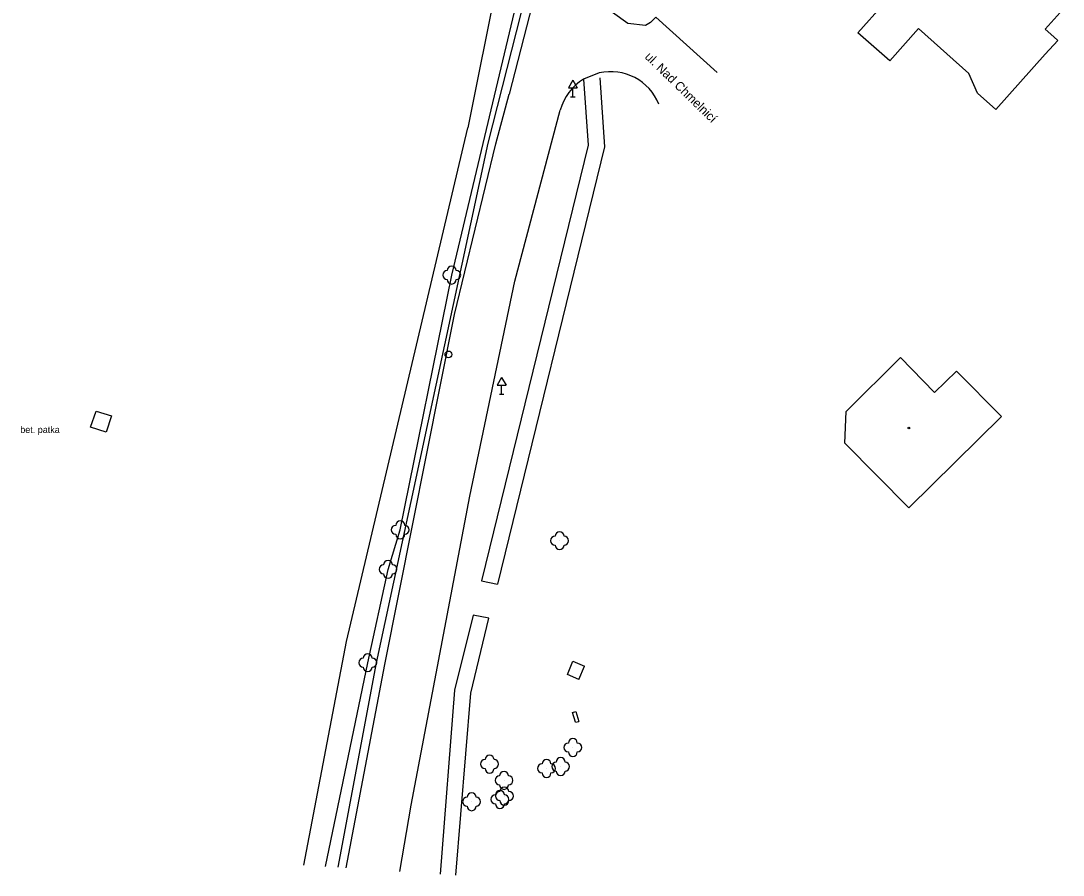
# Model space of a CAD drawing. Extents: x -736687 to -734487, y -1145223 to -1142795.
# Drawn here: x -736687.1 to -736570.8, y -1144307.6 to -1144212.3 of the extents above; entities that cross this region are included whole.
import ezdxf

# ---------------------------------------------------------------- set-up
doc = ezdxf.new("R2010")
doc.units = 0
for name, color, linetype in [('BUDOVY_MĚŘ', 7, 'Continuous'), ('BUOVY_NEMĚŘ', 7, 'Continuous'), ('MAP_ZN_BP', 7, 'Continuous'), ('NÁZVY_ULIC_TOK_SMĚR', 7, 'Continuous'), ('POMOC_POPIS', 7, 'Continuous'), ('ROZHRANÍ_PLOCH', 7, 'Continuous'), ('VÝŠKOPIS', 7, 'Continuous'), ('ZELEŇ', 7, 'Continuous'), ('ZN_BUDOV', 7, 'Continuous'), ('ZN_DOPLŇKOVÉ', 7, 'Continuous')]:
    doc.layers.add(name, color=color, linetype=linetype)

msp = doc.modelspace()

# ---------------------------------------------------------------- linework, layer by layer
at = {"layer": 'BUDOVY_MĚŘ'}
for points in [[(-736593.7, -1144213.67), (-736582.24, -1144200.86), (-736570.79, -1144211.03), (-736572.78, -1144213.27), (-736571.83, -1144214.13)], [(-736572.8, -1144216.07), (-736578.3, -1144222.23), (-736580.34, -1144220.41), (-736581.31, -1144218.21), (-736586.93, -1144213.21), (-736590.14, -1144216.81), (-736593.7, -1144213.67)], [(-736588.01, -1144266.66), (-736595.16, -1144259.45), (-736595, -1144255.91), (-736588.96, -1144249.9), (-736585.15, -1144253.79), (-736582.71, -1144251.42), (-736577.69, -1144256.48), (-736588.01, -1144266.66)], [(-736625.54, -1144289.49), (-736625.18, -1144289.39)], [(-736625.21, -1144290.59), (-736625.54, -1144289.49)], [(-736625.18, -1144289.39), (-736624.85, -1144290.49)], [(-736625.21, -1144290.59), (-736624.85, -1144290.49)]]:
    msp.add_lwpolyline(points, dxfattribs=at)
at = {"layer": 'BUOVY_NEMĚŘ'}
msp.add_lwpolyline([(-736571.83, -1144214.13), (-736571.39, -1144214.52), (-736572.8, -1144216.07)], dxfattribs=at)
at = {"layer": 'MAP_ZN_BP'}
for radius in [0.375, 0.0005]:
    msp.add_circle((-736639.41, -1144249.551), radius, dxfattribs=at)
at = {"layer": 'ROZHRANÍ_PLOCH'}
for points in [[(-736623.31, -1144182.81), (-736627.12, -1144199.12), (-736632.63, -1144220.51)], [(-736609.4, -1144218.09), (-736616.27, -1144211.93), (-736616.85, -1144212.54), (-736617.41, -1144212.85), (-736619.37, -1144212.64), (-736621.08, -1144211.41)], [(-736622.57, -1144218.16), (-736624.32, -1144218.84)], [(-736624.32, -1144218.84), (-736623.8, -1144226.23), (-736635.7, -1144274.81), (-736633.94, -1144275.19)], [(-736622.52, -1144218.71), (-736621.99, -1144226.39), (-736633.94, -1144275.19)], [(-736634.13, -1144226.08), (-736632.63, -1144220.51)], [(-736632.01, -1144241.38), (-736626.94, -1144222.31)], [(-736638.72, -1144245.11), (-736634.13, -1144226.08)], [(-736637, -1144265.35), (-736632.01, -1144241.38)], [(-736646.51, -1144284.13), (-736638.72, -1144245.11)], [(-736643.56, -1144299.82), (-736637, -1144265.35)], [(-736634.88, -1144278.99), (-736636.65, -1144278.63), (-736638.72, -1144286.99), (-736640.32, -1144307.53)], [(-736638.58, -1144307.64), (-736636.92, -1144287.35), (-736634.88, -1144278.99)], [(-736650.84, -1144306.82), (-736646.51, -1144284.13)], [(-736644.82, -1144307.23), (-736643.56, -1144299.82)]]:
    msp.add_lwpolyline(points, dxfattribs=at)
for centre, radius, start, end in [((-736621.285, -1144223.814), 5.798, 22.02059, 102.80325), ((-736621.233, -1144223.895), 5.923, 121.41103, 164.48021)]:
    msp.add_arc(centre, radius, start, end, dxfattribs=at)
at = {"layer": 'VÝŠKOPIS'}
for points in [[(-736639.04, -1144240.7), (-736625.25, -1144182.84)], [(-736634.99, -1144226), (-736628.09, -1144198.92)], [(-736647.44, -1144283.94), (-736634.99, -1144226)], [(-736644.79, -1144269.12), (-736639.04, -1144240.7)], [(-736646.15, -1144273.53), (-736644.79, -1144269.12)], [(-736648.41, -1144283.94), (-736646.15, -1144273.53)], [(-736653.133, -1144306.67), (-736648.41, -1144283.94)], [(-736651.715, -1144306.765), (-736647.44, -1144283.94)]]:
    msp.add_lwpolyline(points, dxfattribs=at)
at = {"layer": 'ZELEŇ'}
for points in [[(-736628.62, -1144184.61), (-736633.96, -1144207.91), (-736637.24, -1144224.27)], [(-736650.78, -1144281.58), (-736637.24, -1144224.27)], [(-736655.56, -1144306.51), (-736650.78, -1144281.58)]]:
    msp.add_lwpolyline(points, dxfattribs=at)
for centre in [(-736639.04, -1144240.7), (-736644.79, -1144269.12), (-736627, -1144270.33), (-736646.15, -1144273.53), (-736648.41, -1144283.94), (-736625.52, -1144293.4), (-736634.82, -1144295.25), (-736628.46, -1144295.74), (-736626.88, -1144295.53), (-736633.2, -1144297.07), (-736636.82, -1144299.45), (-736633.66, -1144299.19), (-736633.16, -1144298.82)]:
    msp.add_circle(centre, 0.0005, dxfattribs=at)
for centre, start, end in [((-736639.54, -1144240.7), 89.99999, 269.99999), ((-736639.04, -1144240.2), 0, 179.99999), ((-736638.54, -1144240.7), 270, 89.99999), ((-736639.04, -1144241.2), 179.99999, 359.99999), ((-736644.79, -1144268.62), 0, 179.99999), ((-736645.29, -1144269.12), 89.99999, 269.99999), ((-736644.29, -1144269.12), 270, 89.99999), ((-736627, -1144269.83), 0, 179.99999), ((-736644.79, -1144269.62), 179.99999, 359.99999), ((-736627.5, -1144270.33), 89.99999, 269.99999), ((-736626.5, -1144270.33), 270, 89.99999), ((-736627, -1144270.83), 179.99999, 359.99999), ((-736646.15, -1144273.03), 0, 179.99999), ((-736646.65, -1144273.53), 89.99999, 269.99999), ((-736646.15, -1144274.03), 179.99999, 359.99999), ((-736645.65, -1144273.53), 270, 89.99999), ((-736648.41, -1144283.44), 0, 179.99999), ((-736648.91, -1144283.94), 89.99999, 269.99999), ((-736648.41, -1144284.44), 179.99999, 359.99999), ((-736647.91, -1144283.94), 270, 89.99999), ((-736625.52, -1144292.9), 0, 179.99999), ((-736626.02, -1144293.4), 89.99999, 269.99999), ((-736625.02, -1144293.4), 270, 89.99999), ((-736635.32, -1144295.25), 89.99999, 269.99999), ((-736634.82, -1144294.75), 0, 179.99999), ((-736634.32, -1144295.25), 270, 89.99999), ((-736628.46, -1144295.24), 0, 179.99999), ((-736626.88, -1144295.03), 0, 179.99999), ((-736625.52, -1144293.9), 179.99999, 359.99999), ((-736634.82, -1144295.75), 179.99999, 359.99999), ((-736633.2, -1144296.57), 0, 179.99999), ((-736628.96, -1144295.74), 89.99999, 269.99999), ((-736627.96, -1144295.74), 270, 89.99999), ((-736627.38, -1144295.53), 89.99999, 269.99999), ((-736626.88, -1144296.03), 179.99999, 359.99999), ((-736626.38, -1144295.53), 270, 89.99999), ((-736633.7, -1144297.07), 89.99999, 269.99999), ((-736632.7, -1144297.07), 270, 89.99999), ((-736628.46, -1144296.24), 179.99999, 359.99999), ((-736636.82, -1144298.95), 0, 179.99999), ((-736633.66, -1144298.69), 0, 179.99999), ((-736633.66, -1144298.82), 89.99999, 269.99999), ((-736633.2, -1144297.57), 179.99999, 359.99999), ((-736633.16, -1144298.32), 0, 179.99999), ((-736632.66, -1144298.82), 270, 89.99999), ((-736637.32, -1144299.45), 89.99999, 269.99999), ((-736636.32, -1144299.45), 270, 89.99999), ((-736634.16, -1144299.19), 89.99999, 269.99999), ((-736633.16, -1144299.32), 179.99999, 359.99999), ((-736633.16, -1144299.19), 270, 89.99999), ((-736636.82, -1144299.95), 179.99999, 359.99999), ((-736633.66, -1144299.69), 179.99999, 359.99999)]:
    msp.add_arc(centre, 0.5, start, end, dxfattribs=at)
at = {"layer": 'ZN_BUDOV'}
msp.add_circle((-736588.01, -1144257.77), 0.0875, dxfattribs=at)
at = {"layer": 'ZN_DOPLŇKOVÉ'}
for p, q in [((-736625.52, -1144218.954), (-736626.02, -1144219.82)), ((-736625.52, -1144218.954), (-736625.02, -1144219.82)), ((-736626.02, -1144219.82), (-736625.02, -1144219.82)), ((-736625.52, -1144220.82), (-736625.52, -1144219.82)), ((-736625.77, -1144220.82), (-736625.27, -1144220.82)), ((-736633.47, -1144252.114), (-736633.97, -1144252.98)), ((-736633.97, -1144252.98), (-736632.97, -1144252.98)), ((-736633.47, -1144252.114), (-736632.97, -1144252.98)), ((-736633.47, -1144253.98), (-736633.47, -1144252.98)), ((-736633.72, -1144253.98), (-736633.22, -1144253.98))]:
    msp.add_line(p, q, dxfattribs=at)
for points in [[(-736679.35, -1144257.66), (-736678.72, -1144255.88), (-736677.02, -1144256.41), (-736677.6, -1144258.22), (-736679.35, -1144257.66)], [(-736626.13, -1144285.25), (-736625.52, -1144283.78)], [(-736625.52, -1144283.78), (-736624.23, -1144284.33)], [(-736624.84, -1144285.8), (-736624.23, -1144284.33)], [(-736624.84, -1144285.8), (-736626.13, -1144285.25)]]:
    msp.add_lwpolyline(points, dxfattribs=at)

# ---------------------------------------------------------------- texts
at = {"layer": 'NÁZVY_ULIC_TOK_SMĚR'}
msp.add_text('ul. Nad Chmelnicí', height=1, rotation=315.72747, dxfattribs=at).set_placement((-736617.56, -1144216.44))
at = {"layer": 'POMOC_POPIS'}
msp.add_text('bet. patka', height=0.75, dxfattribs=at).set_placement((-736687.2, -1144258.32))

doc.saveas('drawing.dxf')
